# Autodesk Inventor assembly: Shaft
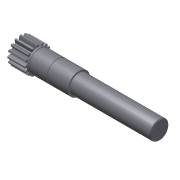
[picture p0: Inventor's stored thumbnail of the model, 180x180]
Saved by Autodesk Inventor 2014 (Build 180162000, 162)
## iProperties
Created: 2010-12
Part Number: Shaft
Document SubType Name: Assembly
Designer: Thom Tremblay
ClientObjectVersion: 1
Author: Thom Tremblay
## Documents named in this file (2)
- C:\Inventor 2014 Essentials\Assemblies\Chapter 08\c08-01\Design Accelerator\Shaft5.iam
- C:\Inventor 2014 Essentials\Assemblies\Chapter 08\c08-01\Design Accelerator\Shaft5.ipt
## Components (1 placed, 1 different names)
1. Shaft:1
